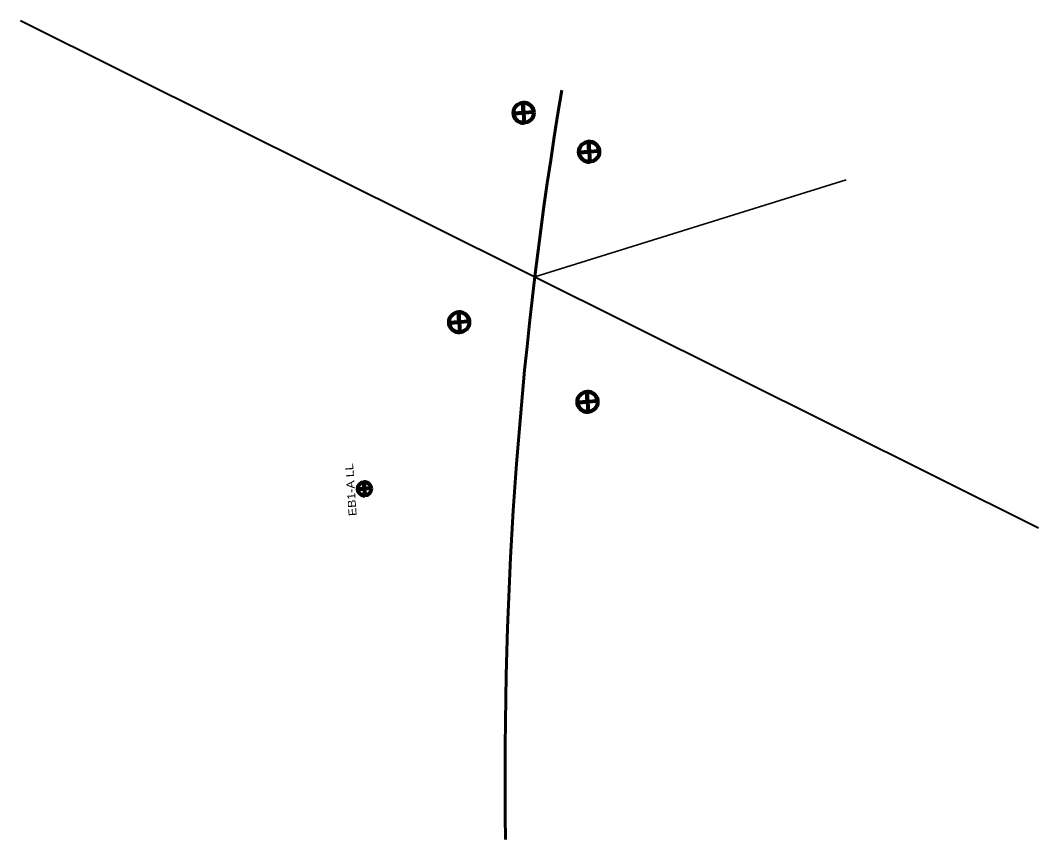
# Model space of a CAD drawing. Extents: x 2399800 to 2400616, y 567347 to 568869.
# Drawn here: x 2399812 to 2400528, y 567347 to 567923 of the extents above; entities that cross this region are included whole.
import ezdxf
from ezdxf.enums import TextEntityAlignment as Align

# ---------------------------------------------------------------- set-up
doc = ezdxf.new("R2010")
doc.units = 0
doc.header["$LTSCALE"] = 2.4
for name, color, linetype, lineweight in [('1', 7, 'Continuous', 40), ('27', 7, 'Continuous', 80), ('4', 7, 'Continuous', 35), ('62', 7, 'Continuous', 60)]:
    doc.layers.add(name, color=color, linetype=linetype, lineweight=lineweight)

msp = doc.modelspace()

# ---------------------------------------------------------------- linework, layer by layer
at = {"layer": '1'}
msp.add_line((2399812.483, 567922.841), (2400528.384, 567565.79), dxfattribs=at)
at = {"layer": '27'}
for p, q in [((2400165.805, 567864.937), (2400166.797, 567850.743)), ((2400159.198, 567857.424), (2400159.204, 567857.345)), ((2400173.398, 567858.336), (2400159.204, 567857.345)), ((2400211.848, 567837.513), (2400212.841, 567823.319)), ((2400205.242, 567830), (2400205.247, 567829.921)), ((2400219.442, 567830.912), (2400205.247, 567829.921)), ((2400120.508, 567717.576), (2400121.501, 567703.381)), ((2400113.902, 567710.062), (2400113.907, 567709.983)), ((2400128.101, 567710.974), (2400113.907, 567709.983)), ((2400210.743, 567661.572), (2400211.736, 567647.378)), ((2400204.137, 567654.059), (2400204.143, 567653.98)), ((2400218.337, 567654.971), (2400204.143, 567653.98)), ((2400054.06, 567598.045), (2400054.722, 567588.582)), ((2400049.656, 567593.037), (2400049.66, 567592.984)), ((2400059.123, 567593.644), (2400049.66, 567592.984))]:
    msp.add_line(p, q, dxfattribs=at)
for points in [[(2400173.398, 567858.336), (2400166.301, 567857.841), (2400165.805, 567864.937), (2400165.726, 567864.932)], [(2400159.204, 567857.345), (2400166.301, 567857.841), (2400166.797, 567850.743)], [(2400219.442, 567830.912), (2400212.345, 567830.417), (2400211.848, 567837.513), (2400211.769, 567837.508)], [(2400205.247, 567829.921), (2400212.345, 567830.417), (2400212.841, 567823.319)], [(2400128.101, 567710.974), (2400121.004, 567710.48), (2400120.508, 567717.576), (2400120.429, 567717.57)], [(2400113.907, 567709.983), (2400121.004, 567710.48), (2400121.501, 567703.381)], [(2400218.337, 567654.971), (2400211.24, 567654.476), (2400210.743, 567661.572), (2400210.665, 567661.567)], [(2400204.143, 567653.98), (2400211.24, 567654.476), (2400211.736, 567647.378)], [(2400059.123, 567593.644), (2400054.391, 567593.314), (2400054.06, 567598.045), (2400054.007, 567598.041)], [(2400049.66, 567592.984), (2400054.391, 567593.314), (2400054.722, 567588.582)]]:
    msp.add_lwpolyline(points, dxfattribs=at)
for centre, radius in [((2400166.301, 567857.841), 7.114), ((2400212.344, 567830.417), 7.114), ((2400121.004, 567710.479), 7.114), ((2400211.24, 567654.476), 7.114), ((2400054.391, 567593.314), 4.743)]:
    msp.add_circle(centre, radius, dxfattribs=at)
for centre, radius, start, end in [((2400166.301, 567857.841), 7.114, 4, 94.64426), ((2400166.301, 567857.841), 7.114, 183.35573, 274), ((2400212.344, 567830.417), 7.114, 4, 94.64426), ((2400212.344, 567830.417), 7.114, 183.35573, 274), ((2400121.004, 567710.479), 7.114, 4, 94.64426), ((2400121.004, 567710.479), 7.114, 183.35573, 274), ((2400211.24, 567654.476), 7.114, 4, 94.64426), ((2400211.24, 567654.476), 7.114, 183.35573, 274), ((2400054.391, 567593.314), 4.743, 4, 94.64426), ((2400054.391, 567593.314), 4.743, 183.35573, 274)]:
    msp.add_arc(centre, radius, start, end, dxfattribs=at)
at = {"layer": '4'}
msp.add_line((2400174.193, 567742.441), (2400393.08, 567810.721), dxfattribs=at)
at = {"layer": '62'}
msp.add_arc((2403053.234, 567394.409), 2900, 170.48821, 180.94658, dxfattribs=at)

# ---------------------------------------------------------------- texts
at = {"layer": '27', "width": 1.15}
msp.add_text('EB1-A LL', height=5.625, rotation=94, dxfattribs=at).set_placement((2400047.638, 567592.83), align=Align.CENTER)

doc.saveas('drawing.dxf')
